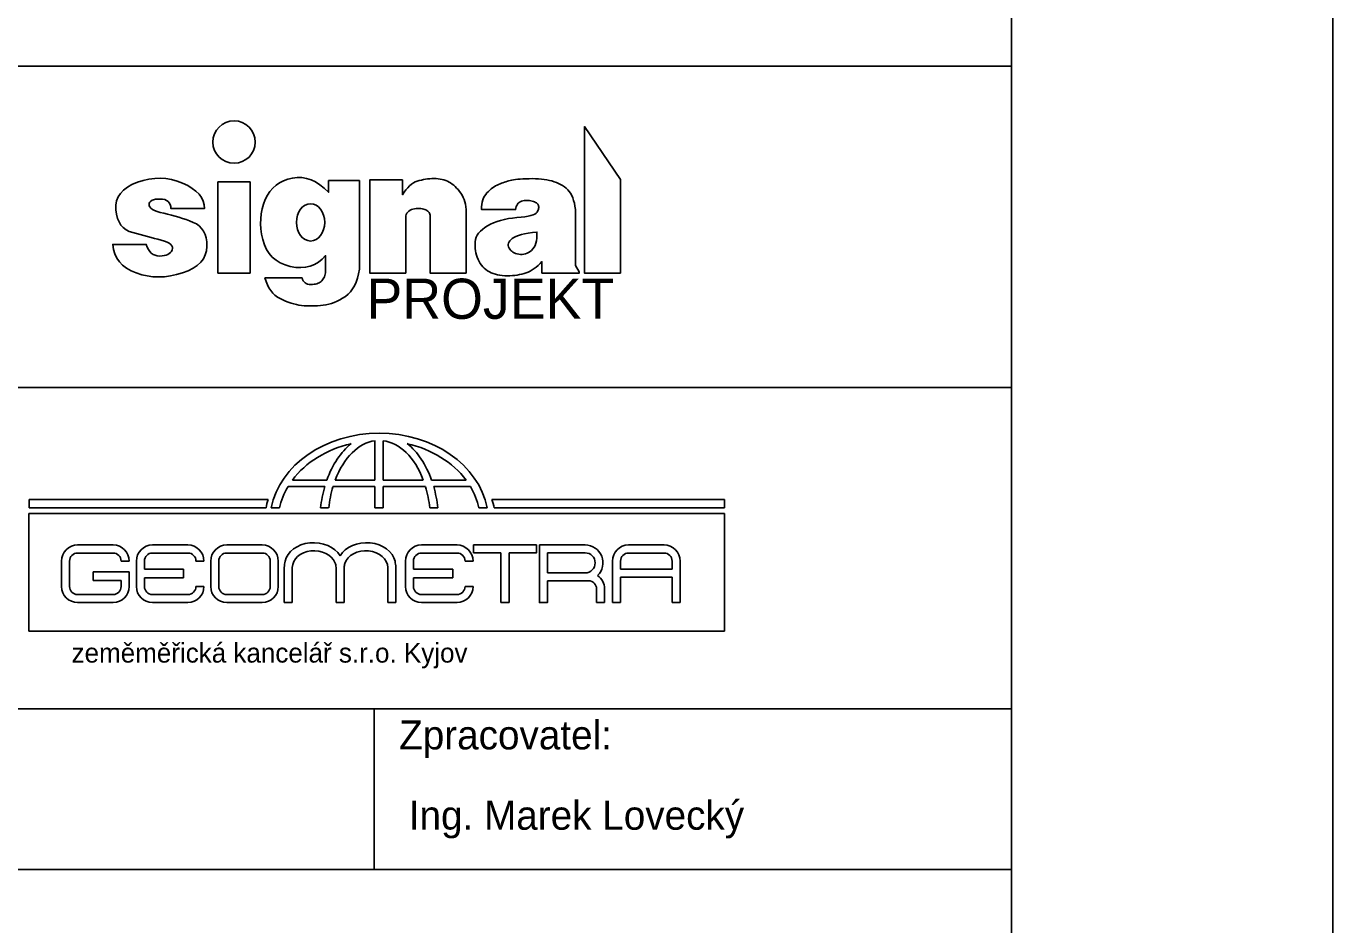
# Model space of a CAD drawing. Extents: x 3181 to 4881, y -5827 to -5382.
# Drawn here: x 4054.2 to 4135.6, y -5727.5 to -5671.5 of the extents above; entities that cross this region are included whole.
import ezdxf

# ---------------------------------------------------------------- set-up
doc = ezdxf.new("R2010")
doc.units = 0
for name, color, linetype in [('Default', 7, 'Continuous'), ('Vrstva 1', 7, 'Continuous'), ('Vrstva 11', 7, 'Continuous'), ('Vrstva 17', 7, 'Continuous'), ('Vrstva 6', 7, 'Continuous')]:
    doc.layers.add(name, color=color, linetype=linetype)

msp = doc.modelspace()

# ---------------------------------------------------------------- linework, layer by layer
at = {"layer": 'Default'}
msp.add_lwpolyline([(3925.563, -5826.032), (4135.563, -5826.032), (4135.563, -5529.032), (3925.563, -5529.032)], close=True, dxfattribs=at)
at = {"layer": 'Vrstva 1'}
msp.add_lwpolyline([(3945.563, -5549.032), (4115.563, -5549.032), (4115.563, -5809.032), (3945.563, -5809.032)], close=True, dxfattribs=at)
at = {"layer": 'Vrstva 11'}
for points in [[(4091.228, -5686.911), (4091.228, -5681.071), (4088.988, -5677.791), (4088.988, -5686.911), (4091.228, -5686.911)], [(4062.499, -5687.146), (4062.861, -5687.13), (4063.228, -5687.082), (4063.599, -5687.003), (4063.975, -5686.893), (4064.329, -5686.756), (4064.637, -5686.6), (4064.898, -5686.424), (4065.112, -5686.228), (4065.28, -5686.012), (4065.4, -5685.776), (4065.474, -5685.521), (4065.5, -5685.245), (4065.49, -5684.971), (4065.451, -5684.722), (4065.385, -5684.498), (4065.291, -5684.299), (4065.17, -5684.124), (4065.021, -5683.974), (4064.844, -5683.849), (4064.639, -5683.748), (4064.42, -5683.662), (4064.198, -5683.58), (4063.973, -5683.503), (4063.747, -5683.43), (4063.518, -5683.361), (4063.287, -5683.297), (4063.054, -5683.237), (4062.818, -5683.182), (4062.596, -5683.127), (4062.405, -5683.068), (4062.244, -5683.005), (4062.114, -5682.938), (4062.014, -5682.867), (4061.945, -5682.791), (4061.906, -5682.712), (4061.897, -5682.629), (4061.914, -5682.55), (4061.95, -5682.481), (4062.006, -5682.423), (4062.082, -5682.376), (4062.178, -5682.339), (4062.294, -5682.314), (4062.429, -5682.299), (4062.585, -5682.296), (4062.74, -5682.306), (4062.875, -5682.335), (4062.99, -5682.383), (4063.085, -5682.448), (4063.16, -5682.532), (4063.214, -5682.635), (4063.249, -5682.755), (4063.263, -5682.894), (4065.342, -5682.894), (4065.323, -5682.652), (4065.261, -5682.422), (4065.156, -5682.205), (4065.008, -5682.001), (4064.817, -5681.809), (4064.583, -5681.631), (4064.307, -5681.464), (4063.987, -5681.311), (4063.645, -5681.182), (4063.3, -5681.087), (4062.952, -5681.027), (4062.602, -5681.002), (4062.249, -5681.012), (4061.894, -5681.057), (4061.535, -5681.137), (4061.174, -5681.252), (4060.836, -5681.394), (4060.547, -5681.557), (4060.306, -5681.74), (4060.114, -5681.944), (4059.971, -5682.168), (4059.876, -5682.413), (4059.83, -5682.679), (4059.832, -5682.964), (4059.872, -5683.246), (4059.938, -5683.498), (4060.03, -5683.72), (4060.148, -5683.913), (4060.293, -5684.076), (4060.464, -5684.21), (4060.661, -5684.315), (4060.885, -5684.389), (4061.12, -5684.449), (4061.351, -5684.509), (4061.578, -5684.568), (4061.802, -5684.627), (4062.023, -5684.686), (4062.239, -5684.744), (4062.452, -5684.802), (4062.662, -5684.86), (4062.854, -5684.92), (4063.016, -5684.984), (4063.146, -5685.053), (4063.246, -5685.126), (4063.314, -5685.204), (4063.352, -5685.287), (4063.359, -5685.374), (4063.335, -5685.465), (4063.289, -5685.553), (4063.228, -5685.629), (4063.152, -5685.694), (4063.062, -5685.747), (4062.958, -5685.789), (4062.84, -5685.819), (4062.707, -5685.837), (4062.559, -5685.844), (4062.411, -5685.833), (4062.275, -5685.8), (4062.152, -5685.744), (4062.04, -5685.666), (4061.942, -5685.565), (4061.855, -5685.441), (4061.781, -5685.294), (4061.72, -5685.126), (4059.639, -5685.126), (4059.683, -5685.433), (4059.767, -5685.715), (4059.89, -5685.973), (4060.052, -5686.206), (4060.254, -5686.416), (4060.496, -5686.601), (4060.778, -5686.762), (4061.099, -5686.899), (4061.442, -5687.008), (4061.79, -5687.085), (4062.142, -5687.131), (4062.499, -5687.146)], [(4068.188, -5686.911), (4068.188, -5681.231), (4066.188, -5681.231), (4066.188, -5686.911), (4068.188, -5686.911)], [(4072.047, -5688.954), (4072.216, -5688.95), (4072.386, -5688.941), (4072.558, -5688.928), (4072.731, -5688.91), (4072.905, -5688.883), (4073.079, -5688.844), (4073.253, -5688.793), (4073.426, -5688.729), (4073.6, -5688.654), (4073.772, -5688.566), (4073.945, -5688.466), (4074.117, -5688.354), (4074.282, -5688.225), (4074.43, -5688.072), (4074.563, -5687.896), (4074.679, -5687.698), (4074.78, -5687.476), (4074.865, -5687.231), (4074.934, -5686.963), (4074.988, -5686.671), (4074.988, -5681.151), (4073.068, -5681.151), (4073.068, -5681.871), (4072.802, -5681.617), (4072.531, -5681.404), (4072.257, -5681.232), (4071.978, -5681.101), (4071.695, -5681.011), (4071.407, -5680.962), (4071.116, -5680.954), (4070.82, -5680.988), (4070.533, -5681.056), (4070.267, -5681.153), (4070.024, -5681.278), (4069.802, -5681.432), (4069.602, -5681.614), (4069.423, -5681.825), (4069.267, -5682.065), (4069.132, -5682.333), (4069.022, -5682.618), (4068.937, -5682.911), (4068.878, -5683.212), (4068.845, -5683.519), (4068.838, -5683.834), (4068.857, -5684.155), (4068.901, -5684.484), (4068.972, -5684.82), (4069.072, -5685.144), (4069.205, -5685.434), (4069.37, -5685.692), (4069.568, -5685.918), (4069.799, -5686.11), (4070.062, -5686.27), (4070.358, -5686.398), (4070.687, -5686.493), (4071.023, -5686.551), (4071.342, -5686.568), (4071.643, -5686.545), (4071.926, -5686.481), (4072.191, -5686.376), (4072.438, -5686.23), (4072.668, -5686.044), (4072.88, -5685.817), (4072.88, -5686.894), (4072.861, -5686.982), (4072.838, -5687.063), (4072.81, -5687.139), (4072.778, -5687.209), (4072.742, -5687.274), (4072.701, -5687.333), (4072.655, -5687.386), (4072.605, -5687.433), (4072.55, -5687.474), (4072.487, -5687.511), (4072.417, -5687.542), (4072.34, -5687.567), (4072.256, -5687.587), (4072.165, -5687.602), (4072.067, -5687.612), (4071.962, -5687.616), (4071.858, -5687.61), (4071.765, -5687.592), (4071.682, -5687.56), (4071.609, -5687.515), (4071.546, -5687.456), (4071.493, -5687.385), (4071.451, -5687.3), (4071.418, -5687.202), (4069.111, -5687.202), (4069.18, -5687.429), (4069.264, -5687.638), (4069.361, -5687.828), (4069.472, -5688), (4069.596, -5688.152), (4069.735, -5688.286), (4069.887, -5688.401), (4070.053, -5688.498), (4070.225, -5688.581), (4070.396, -5688.655), (4070.565, -5688.72), (4070.733, -5688.777), (4070.899, -5688.826), (4071.064, -5688.866), (4071.227, -5688.897), (4071.389, -5688.919), (4071.551, -5688.935), (4071.715, -5688.946), (4071.88, -5688.952), (4072.047, -5688.954)], [(4081.628, -5686.911), (4081.628, -5683.111), (4081.624, -5682.942), (4081.61, -5682.778), (4081.586, -5682.622), (4081.55, -5682.472), (4081.504, -5682.328), (4081.447, -5682.191), (4081.379, -5682.061), (4081.301, -5681.937), (4081.216, -5681.821), (4081.129, -5681.713), (4081.04, -5681.613), (4080.949, -5681.521), (4080.856, -5681.438), (4080.761, -5681.363), (4080.664, -5681.296), (4080.565, -5681.237), (4080.462, -5681.185), (4080.356, -5681.141), (4080.245, -5681.104), (4080.13, -5681.073), (4080.011, -5681.05), (4079.887, -5681.033), (4079.759, -5681.023), (4079.627, -5681.021), (4079.493, -5681.024), (4079.361, -5681.032), (4079.229, -5681.045), (4079.099, -5681.063), (4078.97, -5681.086), (4078.842, -5681.114), (4078.716, -5681.147), (4078.59, -5681.184), (4078.467, -5681.233), (4078.345, -5681.297), (4078.226, -5681.379), (4078.11, -5681.476), (4077.996, -5681.59), (4077.884, -5681.721), (4077.775, -5681.868), (4077.668, -5682.031), (4077.668, -5681.111), (4075.628, -5681.111), (4075.628, -5686.911), (4077.868, -5686.911), (4077.868, -5683.351), (4077.902, -5683.26), (4077.946, -5683.179), (4078.001, -5683.108), (4078.065, -5683.047), (4078.139, -5682.996), (4078.223, -5682.955), (4078.317, -5682.924), (4078.421, -5682.903), (4078.527, -5682.89), (4078.628, -5682.883), (4078.723, -5682.883), (4078.814, -5682.888), (4078.899, -5682.899), (4078.978, -5682.917), (4079.053, -5682.941), (4079.122, -5682.97), (4079.184, -5683.005), (4079.238, -5683.044), (4079.284, -5683.086), (4079.321, -5683.131), (4079.35, -5683.181), (4079.371, -5683.234), (4079.383, -5683.291), (4079.388, -5683.351), (4079.388, -5686.911), (4081.628, -5686.911)], [(4084.19, -5687.075), (4084.352, -5687.073), (4084.51, -5687.064), (4084.663, -5687.05), (4084.812, -5687.03), (4084.956, -5687.004), (4085.097, -5686.972), (4085.233, -5686.935), (4085.364, -5686.892), (4085.493, -5686.841), (4085.62, -5686.779), (4085.746, -5686.707), (4085.869, -5686.625), (4085.991, -5686.532), (4086.112, -5686.429), (4086.23, -5686.315), (4086.348, -5686.191), (4086.348, -5686.911), (4088.668, -5686.911), (4088.668, -5686.831), (4088.428, -5686.431), (4088.428, -5682.951), (4088.401, -5682.747), (4088.365, -5682.557), (4088.32, -5682.381), (4088.265, -5682.22), (4088.201, -5682.073), (4088.127, -5681.941), (4088.043, -5681.823), (4087.95, -5681.719), (4087.849, -5681.627), (4087.742, -5681.541), (4087.628, -5681.462), (4087.508, -5681.39), (4087.382, -5681.325), (4087.25, -5681.267), (4087.111, -5681.216), (4086.966, -5681.172), (4086.814, -5681.134), (4086.655, -5681.102), (4086.489, -5681.075), (4086.315, -5681.055), (4086.135, -5681.04), (4085.947, -5681.03), (4085.751, -5681.027), (4085.549, -5681.029), (4085.35, -5681.035), (4085.166, -5681.043), (4084.997, -5681.054), (4084.843, -5681.066), (4084.703, -5681.081), (4084.578, -5681.098), (4084.467, -5681.118), (4084.372, -5681.14), (4084.283, -5681.163), (4084.194, -5681.189), (4084.104, -5681.217), (4084.013, -5681.246), (4083.921, -5681.278), (4083.829, -5681.311), (4083.737, -5681.346), (4083.643, -5681.384), (4083.55, -5681.425), (4083.458, -5681.474), (4083.366, -5681.529), (4083.276, -5681.592), (4083.187, -5681.661), (4083.099, -5681.736), (4083.012, -5681.819), (4082.926, -5681.909), (4082.845, -5682.006), (4082.776, -5682.113), (4082.718, -5682.229), (4082.67, -5682.355), (4082.633, -5682.49), (4082.607, -5682.634), (4082.592, -5682.788), (4082.588, -5682.951), (4084.708, -5682.951), (4084.723, -5682.855), (4084.747, -5682.768), (4084.78, -5682.69), (4084.821, -5682.621), (4084.872, -5682.561), (4084.93, -5682.511), (4084.998, -5682.469), (4085.073, -5682.437), (4085.154, -5682.413), (4085.235, -5682.395), (4085.317, -5682.384), (4085.399, -5682.379), (4085.481, -5682.381), (4085.565, -5682.389), (4085.648, -5682.404), (4085.732, -5682.425), (4085.813, -5682.45), (4085.884, -5682.478), (4085.947, -5682.508), (4086, -5682.54), (4086.045, -5682.574), (4086.082, -5682.611), (4086.109, -5682.649), (4086.128, -5682.69), (4086.14, -5682.733), (4086.145, -5682.778), (4086.144, -5682.827), (4086.136, -5682.878), (4086.122, -5682.932), (4086.103, -5682.989), (4086.076, -5683.049), (4086.044, -5683.112), (4085.993, -5683.173), (4085.912, -5683.229), (4085.801, -5683.28), (4085.659, -5683.325), (4085.487, -5683.365), (4085.285, -5683.4), (4085.052, -5683.429), (4084.789, -5683.453), (4084.517, -5683.48), (4084.258, -5683.517), (4084.01, -5683.565), (4083.775, -5683.624), (4083.553, -5683.693), (4083.342, -5683.772), (4083.144, -5683.862), (4082.958, -5683.963), (4082.789, -5684.071), (4082.641, -5684.184), (4082.513, -5684.301), (4082.407, -5684.423), (4082.321, -5684.549), (4082.256, -5684.68), (4082.212, -5684.815), (4082.189, -5684.955), (4082.181, -5685.096), (4082.182, -5685.236), (4082.192, -5685.375), (4082.211, -5685.513), (4082.239, -5685.65), (4082.276, -5685.785), (4082.322, -5685.919), (4082.377, -5686.053), (4082.44, -5686.181), (4082.51, -5686.3), (4082.587, -5686.41), (4082.671, -5686.512), (4082.761, -5686.604), (4082.859, -5686.688), (4082.964, -5686.763), (4083.075, -5686.829), (4083.193, -5686.887), (4083.317, -5686.937), (4083.447, -5686.979), (4083.584, -5687.014), (4083.726, -5687.041), (4083.875, -5687.06), (4084.03, -5687.072), (4084.19, -5687.075)], [(4084.906, -5685.731), (4084.803, -5685.71), (4084.708, -5685.682), (4084.622, -5685.646), (4084.543, -5685.603), (4084.472, -5685.551), (4084.409, -5685.492), (4084.354, -5685.426), (4084.307, -5685.351), (4084.273, -5685.273), (4084.255, -5685.196), (4084.254, -5685.12), (4084.27, -5685.045), (4084.302, -5684.971), (4084.351, -5684.898), (4084.417, -5684.826), (4084.5, -5684.754), (4084.603, -5684.686), (4084.732, -5684.623), (4084.886, -5684.565), (4085.065, -5684.513), (4085.269, -5684.465), (4085.498, -5684.424), (4085.753, -5684.387), (4086.032, -5684.356), (4086.037, -5684.554), (4086.028, -5684.736), (4086.006, -5684.902), (4085.972, -5685.052), (4085.924, -5685.186), (4085.864, -5685.303), (4085.79, -5685.404), (4085.704, -5685.49), (4085.611, -5685.561), (4085.515, -5685.62), (4085.418, -5685.668), (4085.319, -5685.704), (4085.219, -5685.728), (4085.116, -5685.741), (4085.012, -5685.742), (4084.906, -5685.731)]]:
    msp.add_lwpolyline(points, dxfattribs=at)
msp.add_circle((4067.188, -5678.751), 1.32, dxfattribs=at)
msp.add_ellipse((4071.948, -5683.751), major_axis=(0, 1.16), ratio=0.758621, dxfattribs=at)
at = {"layer": 'Vrstva 17'}
for p, q in [((4075.958, -5697.345), (4075.958, -5699.791)), ((4076.465, -5699.791), (4076.465, -5697.343)), ((4072.965, -5699.791), (4070.82, -5699.791)), ((4075.958, -5699.791), (4073.482, -5699.791)), ((4078.96, -5699.791), (4076.465, -5699.791)), ((4081.622, -5699.791), (4079.477, -5699.791)), ((4070.545, -5700.202), (4072.832, -5700.202)), ((4073.342, -5700.202), (4075.958, -5700.202)), ((4075.958, -5700.202), (4075.958, -5701.523)), ((4076.465, -5701.523), (4076.465, -5700.202)), ((4076.465, -5700.202), (4079.099, -5700.202)), ((4079.609, -5700.202), (4081.897, -5700.202)), ((4069.314, -5700.991), (4054.433, -5700.991)), ((4054.433, -5700.991), (4054.433, -5701.523)), ((4054.433, -5701.523), (4069.176, -5701.523)), ((4069.502, -5701.523), (4070.019, -5701.523)), ((4072.575, -5701.523), (4073.075, -5701.523)), ((4075.958, -5701.523), (4076.465, -5701.523)), ((4079.366, -5701.523), (4079.866, -5701.523)), ((4082.423, -5701.523), (4082.94, -5701.523)), ((4097.712, -5700.991), (4083.233, -5700.991)), ((4083.371, -5701.523), (4097.712, -5701.523)), ((4097.712, -5701.523), (4097.712, -5700.991)), ((4097.71, -5701.867), (4054.427, -5701.867)), ((4054.427, -5701.867), (4054.427, -5709.205)), ((4097.71, -5709.205), (4097.71, -5701.867)), ((4057.452, -5703.833), (4059.663, -5703.833)), ((4062.108, -5703.833), (4064.319, -5703.833)), ((4066.732, -5703.833), (4068.943, -5703.833)), ((4078.851, -5703.833), (4081.061, -5703.833)), ((4086.188, -5703.833), (4089.032, -5703.833)), ((4091.736, -5703.833), (4093.947, -5703.833)), ((4056.454, -5706.417), (4056.454, -5704.831)), ((4056.953, -5704.831), (4056.953, -5706.417)), ((4059.663, -5704.332), (4057.452, -5704.332)), ((4060.66, -5704.831), (4060.162, -5704.831)), ((4061.11, -5706.417), (4061.11, -5704.831)), ((4061.609, -5704.831), (4061.609, -5705.341)), ((4064.319, -5704.332), (4062.108, -5704.332)), ((4065.317, -5704.831), (4064.818, -5704.831)), ((4065.734, -5706.417), (4065.734, -5704.831)), ((4066.233, -5704.831), (4066.233, -5706.417)), ((4068.943, -5704.332), (4066.732, -5704.332)), ((4069.442, -5706.417), (4069.442, -5704.831)), ((4069.941, -5704.831), (4069.941, -5706.417)), ((4077.853, -5706.417), (4077.853, -5704.831)), ((4078.352, -5704.831), (4078.352, -5705.341)), ((4081.061, -5704.332), (4078.851, -5704.332)), ((4082.059, -5704.831), (4081.56, -5704.831)), ((4083.794, -5707.415), (4083.794, -5704.32)), ((4084.297, -5704.32), (4084.297, -5707.415)), ((4089.032, -5704.322), (4086.692, -5704.322)), ((4086.692, -5704.322), (4086.692, -5705.572)), ((4090.738, -5707.415), (4090.738, -5704.831)), ((4091.237, -5704.831), (4091.237, -5705.339)), ((4093.947, -5704.332), (4091.736, -5704.332)), ((4094.446, -5705.339), (4094.446, -5704.831)), ((4094.945, -5704.831), (4094.945, -5707.415)), ((4058.427, -5706.039), (4058.427, -5705.494)), ((4058.427, -5705.494), (4060.66, -5705.494)), ((4060.66, -5705.494), (4060.66, -5706.417)), ((4061.609, -5705.341), (4064.052, -5705.341)), ((4064.052, -5705.341), (4064.052, -5705.886)), ((4070.313, -5707.415), (4070.313, -5705.23)), ((4070.814, -5705.23), (4070.814, -5707.415)), ((4073.533, -5707.415), (4073.533, -5705.23)), ((4074.033, -5705.23), (4074.033, -5707.415)), ((4076.752, -5707.415), (4076.752, -5705.23)), ((4077.253, -5705.23), (4077.253, -5707.415)), ((4078.352, -5705.341), (4080.795, -5705.341)), ((4080.795, -5705.341), (4080.795, -5705.886)), ((4086.692, -5705.572), (4089.032, -5705.572)), ((4091.237, -5705.339), (4094.446, -5705.339)), ((4060.162, -5706.039), (4058.427, -5706.039)), ((4060.162, -5706.417), (4060.162, -5706.039)), ((4064.052, -5705.886), (4061.609, -5705.886)), ((4061.609, -5705.886), (4061.609, -5706.417)), ((4064.818, -5706.417), (4065.317, -5706.417)), ((4080.795, -5705.886), (4078.352, -5705.886)), ((4078.352, -5705.886), (4078.352, -5706.417)), ((4081.56, -5706.417), (4082.059, -5706.417)), ((4089.032, -5706.06), (4086.692, -5706.06)), ((4089.247, -5706.064), (4089.032, -5706.06)), ((4089.746, -5707.415), (4089.746, -5706.563)), ((4090.244, -5706.563), (4090.244, -5707.415)), ((4094.446, -5705.843), (4091.237, -5705.843)), ((4091.237, -5705.843), (4091.237, -5707.415)), ((4094.446, -5707.415), (4094.446, -5705.843)), ((4057.452, -5706.916), (4059.663, -5706.916)), ((4062.108, -5706.916), (4064.319, -5706.916)), ((4066.732, -5706.916), (4068.943, -5706.916)), ((4078.851, -5706.916), (4081.061, -5706.916)), ((4059.663, -5707.415), (4057.452, -5707.415)), ((4064.319, -5707.415), (4062.108, -5707.415)), ((4068.943, -5707.415), (4066.732, -5707.415)), ((4070.814, -5707.415), (4070.313, -5707.415)), ((4074.033, -5707.415), (4073.533, -5707.415)), ((4077.253, -5707.415), (4076.752, -5707.415)), ((4081.061, -5707.415), (4078.851, -5707.415)), ((4084.297, -5707.415), (4083.794, -5707.415)), ((4090.244, -5707.415), (4089.746, -5707.415)), ((4091.237, -5707.415), (4090.738, -5707.415)), ((4094.945, -5707.415), (4094.446, -5707.415)), ((4054.427, -5709.205), (4097.71, -5709.205))]:
    msp.add_line(p, q, dxfattribs=at)
for points in [[(4083.794, -5704.32), (4082.096, -5704.32), (4082.096, -5703.833), (4086.009, -5703.833)], [(4086.009, -5703.833), (4086.009, -5704.32), (4084.297, -5704.32)], [(4086.692, -5706.06), (4086.692, -5707.415), (4086.188, -5707.415), (4086.188, -5703.833)]]:
    msp.add_lwpolyline(points, dxfattribs=at)
for centre, radius, start, end in [((4057.452, -5704.831), 0.998, 90, 180), ((4059.663, -5704.831), 0.998, 360, 90), ((4062.108, -5704.831), 0.998, 90, 180), ((4064.319, -5704.831), 0.998, 360, 90), ((4066.732, -5704.831), 0.998, 90, 180), ((4068.943, -5704.831), 0.998, 360, 90), ((4078.851, -5704.831), 0.998, 90, 180), ((4081.061, -5704.831), 0.998, 360, 90), ((4089.032, -5704.947), 1.114, 314.45734, 90), ((4091.736, -5704.831), 0.998, 90, 180), ((4093.947, -5704.831), 0.998, 360, 90), ((4057.452, -5704.831), 0.499, 90, 180), ((4059.663, -5704.831), 0.499, 0, 90), ((4062.108, -5704.831), 0.499, 90, 180), ((4064.319, -5704.831), 0.499, 0, 90), ((4066.732, -5704.831), 0.499, 90, 180), ((4068.943, -5704.831), 0.499, 0, 90), ((4072.25, -5705.28), 1.938, 166.96576, 178.52091), ((4072.579, -5705.294), 0.957, 3.86486, 22.41569), ((4075.315, -5705.28), 1.938, 1.47909, 13.03424), ((4078.851, -5704.831), 0.499, 90, 180), ((4081.061, -5704.831), 0.499, 0, 90), ((4089.032, -5704.947), 0.625, 270, 90), ((4091.736, -5704.831), 0.499, 90, 180), ((4093.947, -5704.831), 0.499, 0, 90), ((4075.266, -5705.352), 1.238, 162.61388, 174.3506), ((4089.247, -5706.563), 0.998, 360, 55.44734), ((4057.452, -5706.417), 0.998, 180, 270), ((4057.452, -5706.417), 0.499, 180, 270), ((4059.663, -5706.417), 0.998, 270, 0), ((4059.663, -5706.417), 0.499, 270, 0), ((4062.108, -5706.417), 0.998, 180, 270), ((4062.108, -5706.417), 0.499, 180, 270), ((4064.319, -5706.417), 0.998, 270, 0), ((4064.319, -5706.417), 0.499, 270, 0), ((4066.732, -5706.417), 0.998, 180, 270), ((4066.732, -5706.417), 0.499, 180, 270), ((4068.943, -5706.417), 0.998, 270, 0), ((4068.943, -5706.417), 0.499, 270, 0), ((4078.851, -5706.417), 0.998, 180, 270), ((4078.851, -5706.417), 0.499, 180, 270), ((4081.061, -5706.417), 0.998, 270, 0), ((4081.061, -5706.417), 0.499, 270, 0), ((4089.247, -5706.563), 0.499, 0, 90)]:
    msp.add_arc(centre, radius, start, end, dxfattribs=at)
for centre, major_axis, ratio, start_param, end_param in [((4076.221, -5702.395), (-6.804, 0), 0.811768, 3.300239, 6.124539), ((4076.221, -5702.395), (-6.296, 0), 0.804826, 4.992897, 5.743383), ((4076.221, -5702.395), (0, 5.524), 0.668443, 0.491666, 1.079789), ((4076.221, -5702.395), (0, 5.067), 0.630136, 0.08224, 1.030995), ((4076.221, -5702.395), (0, 5.067), 0.630136, 5.252191, 6.206521), ((4076.221, -5702.395), (0, 5.524), 0.668443, 5.203397, 5.79152), ((4076.221, -5702.395), (-6.296, 0), 0.804826, 3.681394, 4.431881), ((4076.221, -5702.395), (-6.296, 0), 0.804826, 5.835664, 6.110118), ((4076.221, -5702.395), (0, 5.524), 0.668443, 1.16256, 1.41215), ((4076.221, -5702.395), (0, 5.067), 0.630136, 1.123275, 1.397729), ((4076.221, -5702.395), (0, 5.067), 0.630136, 4.885456, 5.159911), ((4076.221, -5702.395), (0, 5.524), 0.668443, 4.871035, 5.120625), ((4076.221, -5702.395), (-6.296, 0), 0.804826, 3.31466, 3.589114), ((4075.895, -5702.395), (-6.804, 0), 0.811768, 6.026233, 6.124539), ((4076.653, -5702.395), (-6.804, 0), 0.811768, 3.300239, 3.398545), ((4072.142, -5705.074), (1.805, 0), 0.766187, 0.429647, 2.97338), ((4075.424, -5705.074), (-1.805, 0), 0.766187, 3.309805, 5.853538), ((4072.167, -5705.23), (1.354, 0), 0.766187, 0.29376, 3.141593), ((4075.398, -5705.23), (-1.354, 0), 0.766187, 3.141593, 6.041607)]:
    msp.add_ellipse(centre, major_axis=major_axis, ratio=ratio, start_param=start_param, end_param=end_param, dxfattribs=at)
at = {"layer": 'Vrstva 6'}
for p, q in [((3945.563, -5694.032), (4115.563, -5694.032)), ((3945.563, -5714.032), (4115.563, -5714.032)), ((4075.913, -5724.032), (4075.913, -5714.032))]:
    msp.add_line(p, q, dxfattribs=at)
msp.add_lwpolyline([(3945.563, -5674.032), (4115.563, -5674.032), (4115.563, -5724.032), (3945.563, -5724.032)], close=True, dxfattribs=at)

# ---------------------------------------------------------------- texts
at = {"layer": 'Vrstva 11'}
msp.add_text('PROJEKT', height=2.5, dxfattribs=at).set_placement((4075.428, -5689.754))
at = {"layer": 'Vrstva 17'}
msp.add_text('zeměměřická kancelář s.r.o. Kyjov', height=1.20984, dxfattribs=at).set_placement((4057.079, -5711.154))
at = {"layer": 'Vrstva 6'}
for s, p in [('Zpracovatel:', (4077.459, -5716.559)), ('Ing. Marek Lovecký', (4078.06, -5721.559))]:
    msp.add_text(s, height=1.8, dxfattribs=at).set_placement(p)

doc.saveas('drawing.dxf')
